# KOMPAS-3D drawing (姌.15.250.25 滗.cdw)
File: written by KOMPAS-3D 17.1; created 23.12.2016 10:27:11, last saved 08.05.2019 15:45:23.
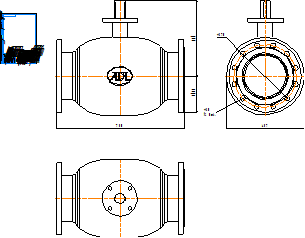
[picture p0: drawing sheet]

Sheet 1: A4, portrait

Title block, sheet 1: name: КШ.15.250.25 фф; material: Внимание! Данный продукт является объектом авторского права ООО «Торговый Дом АДЛ». / Запрещается изменение, копирование, распространение / (в том числе путем копирования на другие сайты и ресурсы в Интернете) / или любое иное использование информации и объектов без предварительного / согласия правообладателя (ООО «Торговый Дом АДЛ»).; sheets: 1; organisation: ООО "Торговый дом АДЛ"; sheet format: A4; stored path: C:\Users\tra\Desktop\2д чертежи\Шаровые краны БИВАЛ\КШ_Бивал_серия_14_15\KOMPAS_2D\КШ.15.250.25 фф.cdw

Views: Вид 1, Проекционный вид 2, Проекционный вид 3
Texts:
  Klimkovich
  ADL
Dimensions and other numbers on the sheet: 750; 441; 212,5; 457; 370; 30; 12 Отв.; 1:1; 1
